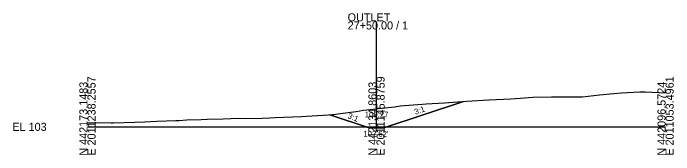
# Model space of a CAD drawing. Extents: x -26 to 1203, y -15 to 9526.
# Drawn here: x 974.3 to 1202.8, y 7490.3 to 7539.4 of the extents above; entities that cross this region are included whole.
import ezdxf

# ---------------------------------------------------------------- set-up
doc = ezdxf.new("R2010")
doc.units = 0
for name, color, linetype in [('Default', 7, 'Continuous'), ('Exist Cross Section Cell', 7, 'Continuous'), ('Exist XS Center Line Elevation Label', 7, 'Continuous'), ('Exist XS Ground Line', 7, 'Continuous'), ('Prop XS DDE', 7, 'Continuous'), ('Prop XS DDE Earthwork Shape', 7, 'Continuous'), ('Prop XS DDE Elevations', 7, 'Continuous'), ('Prop XS DDE Slope Text', 7, 'Continuous')]:
    doc.layers.add(name, color=color, linetype=linetype)

msp = doc.modelspace()

# ---------------------------------------------------------------- linework, layer by layer
at = {"layer": 'Exist Cross Section Cell'}
for p, q in [((1100, 7500), (1100, 7536.52)), ((1000, 7500), (1100, 7500)), ((1100, 7500), (1200, 7500))]:
    msp.add_line(p, q, dxfattribs=at)
at = {"layer": 'Exist XS Ground Line'}
msp.add_lwpolyline([(1000, 7501.44), (1008.22, 7501.36), (1008.94, 7501.39), (1016.38, 7501.6), (1019.76, 7501.71), (1024.03, 7501.93), (1030.59, 7502.19), (1031.69, 7502.24), (1034.34, 7502.44), (1039.34, 7502.58), (1041.41, 7502.64), (1046.99, 7502.81), (1052.24, 7502.96), (1054.65, 7502.94), (1060.46, 7503.05), (1063.06, 7503.13), (1064.9, 7503.19), (1073.89, 7503.53), (1083.39, 7504.13), (1084.71, 7504.23), (1085.26, 7504.29), (1086.58, 7504.46), (1092.91, 7505.34), (1095.54, 7505.72), (1100, 7506.27), (1100.56, 7506.34), (1106.36, 7506.97), (1108.22, 7507.22), (1112.69, 7507.61), (1115.87, 7507.89), (1117.19, 7508), (1123.52, 7508.34), (1128.01, 7508.66), (1131.18, 7508.89), (1138.84, 7509.37), (1146.48, 7509.7), (1149.66, 7509.93), (1154.13, 7510.22), (1160.48, 7510.34), (1161.79, 7510.36), (1164.93, 7510.36), (1169.44, 7510.42), (1171.31, 7510.41), (1177.09, 7511.13), (1182.13, 7511.55), (1184.75, 7511.77), (1191.05, 7512.09), (1192.4, 7512.17), (1192.96, 7512.14), (1200, 7511.78)], dxfattribs=at)
at = {"layer": 'Prop XS DDE'}
for p, q in [((1102.5, 7499.62), (1130.05, 7508.8)), ((1083.85, 7504.17), (1097.5, 7499.62)), ((1097.5, 7499.62), (1102.5, 7499.62))]:
    msp.add_line(p, q, dxfattribs=at)
at = {"layer": 'Prop XS DDE Earthwork Shape'}
msp.add_lwpolyline([(1083.85, 7504.17), (1084.71, 7504.23), (1085.26, 7504.29), (1086.58, 7504.46), (1092.91, 7505.34), (1095.54, 7505.72), (1100, 7506.27), (1100.56, 7506.34), (1106.36, 7506.97), (1108.22, 7507.22), (1112.69, 7507.61), (1115.87, 7507.89), (1117.19, 7508), (1123.52, 7508.34), (1128.01, 7508.66), (1130.05, 7508.8), (1102.5, 7499.62), (1097.5, 7499.62)], close=True, dxfattribs=at)

# ---------------------------------------------------------------- texts
at = {"layer": 'Default'}
msp.add_text("102.62'", height=2, dxfattribs=at).set_placement((1095.44, 7496.58))
at = {"layer": 'Exist Cross Section Cell'}
for s, p in [('OUTLET', (1090, 7536.52)), ('27+50.00 / 1', (1090, 7533.72)), ('EL 103', (974, 7498.6))]:
    msp.add_text(s, height=2.8, dxfattribs=at).set_placement(p)
for s, p in [('E 2011238.2557', (1002.8, 7490)), ('E 2011145.8759', (1102.8, 7490)), ('E 2011053.4961', (1202.8, 7490)), ('N 442173.1483', (1000, 7490)), ('N 442134.8603', (1100, 7490)), ('N 442096.5724', (1200, 7490))]:
    msp.add_text(s, height=2.8, rotation=90, dxfattribs=at).set_placement(p)
at = {"layer": 'Exist XS Center Line Elevation Label'}
msp.add_text('109.27', height=2, dxfattribs=at).set_placement((1095.94, 7503.27))
at = {"layer": 'Prop XS DDE Elevations'}
msp.add_text("102.62'", height=2, dxfattribs=at).set_placement((1095.44, 7496.58))
at = {"layer": 'Prop XS DDE Slope Text'}
for rotation, p in [(19.4493, (1113.44, 7504.14)), (339.0265, (1089.84, 7503.02))]:
    msp.add_text('3:1', height=2, rotation=rotation, dxfattribs=at).set_placement(p)

doc.saveas('drawing.dxf')
